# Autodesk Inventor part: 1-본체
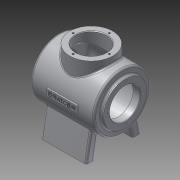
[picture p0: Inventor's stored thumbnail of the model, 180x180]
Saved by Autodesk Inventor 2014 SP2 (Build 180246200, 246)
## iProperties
Created: 2015-01
Part Number: 1-본체
Material: 알루미늄 6061
Document SubType Name: Modeling
Designer: 201-07
Density: 2.71 g/cm^3
Appearance: 알루미늄 - 평지
Mass: 1021.13 g
Surface Area: 1060.37 cm^2
Volume: 376.801 cm^3
Author: 201-07
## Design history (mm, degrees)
sketch "스케치1"
  geometry: C1 r 50 at (0, 0); 1 further point
  constraints: 1 centre point, 1 coincident
  dimensions: "d0" = 100 diameter of C1
extrude "돌출1" new body sketch "스케치1" stored distance "d1" = 112; taper "d2" = 0 deg
fillet "모깎기1" dims "d3" = 3
node "작업 평면1"
sketch "스케치2"
  geometry: C1 r 38 at (0, 0); 1 further point
  constraints: 1 centre point, 1 coincident
  dimensions: "d5" = 76 diameter of C1
extrude "돌출2" join sketch "스케치2" stored distance "d6" = 112; taper "d7" = 0 deg
fillet "모깎기2" dims "d8" = 3
fillet "모깎기3" dims "d9" = 3
hole "구멍1" diameter "d12" = 54; stored, may be unused: countersink angle "d16" = 90 deg, drill point angle "d18" = 0 deg; dims "d10" = 10, "d11" = 10, "d13" = 6, "d14" = 4, "d15" = 2, "d17" = 13
hole "구멍2" diameter "d21" = 90; stored, may be unused: countersink angle "d25" = 90 deg, drill point angle "d27" = 0 deg; dims "d19" = 10, "d20" = 10, "d22" = 6, "d23" = 4, "d24" = 2, "d26" = 97
hole "구멍3" diameter "d30" = 54; stored, may be unused: countersink angle "d34" = 90 deg, drill point angle "d36" = 0 deg; dims "d28" = 10, "d29" = 10, "d31" = 6, "d32" = 4, "d33" = 2, "d35" = 12
node "작업 평면2"
sketch "스케치3"
  geometry: L1 (-61, 38)-(-61, -38) reference; L2 (0, 0)-(1, 0); C1 r 38 at (1, 0)
  constraints: 2 end point, 1 centre point, 1 perpendicular
  dimensions: "d103" = 76 diameter of C1; "d104" = 62 distance from line of L1 L2.end
extrude "돌출3" join sketch "스케치3" stored distance "d39" = 112; taper "d40" = 0 deg
sketch "스케치5" dims "d62" = 64
  geometry: L1 (-32, 0)-(0, 0); 1 further point
  constraints: 2 end point, 1 coincident, 1 horizontal, 1 horizontal alignment, 2 other
hole "구멍6" sketch "스케치5" at (-32, 0) diameter "d63" = 3.242; stored, may be unused: countersink angle "d67" = 90 deg, drill point angle "d69" = 118 deg; dims "d64" = 8, "d65" = 4, "d66" = 2, "d68" = 10
chamfer "모따기1" distance "d73" = 1; stored, may be unused: second distance "d74" = 2, angle "d75" = 45 deg
fillet "모깎기5" dims "d76" = 3
node "작업 평면3"
sketch "스케치6"
  geometry: L1 (39.336, -30.865)-(48, -80); L2 (27.282, -41.901)-(34, -80); L3 (48, -80)-(34, -80); C1 r 45 at (0, 0) reference; A1 r 50 centre (0, 0) between (8.491, 49.274) and (-8.491, 49.274); A2 r 50 centre (0, 0) between (27.282, -41.901) and (39.336, -30.865); 2 further points
  constraints: 6 end point, 4 point on circle, 2 centre point, 1 coincident, 1 horizontal, 1 parallel, 2 other
  dimensions: "d78" = 80 distance from line of point (0, 0) L3; "d79" = 14 distance of L2.end L1.end; "d80" = 100 deg angle of L3 L1; "d81" = 80 deg angle of L3 L2 (derived); "d84" = 48 horizontal distance of point (0, 0) L1.end
extrude "돌출4" join sketch "스케치6" distance "d85" = 80; taper "d86" = 0 deg
fillet "모깎기6" dims "d87" = 3
node "작업 평면4"
sketch "스케치7"
  geometry: L1 (-26, 6)-(28, 6); L2 (28, 6)-(28, -6); L3 (28, -6)-(-26, -6); L4 (-26, -6)-(-26, 6); L5 (-26, 6)-(28, -6); L6 (28, 6)-(-26, -6); L7 (37, -80)-(-37, -80) reference; L8 (-61, 38)-(-61, -38) reference; 1 further point
  constraints: 12 end point, 2 midpoint, 2 parallel, 1 horizontal, 1 perpendicular
  dimensions: "d98" = 12 distance between parallel lines of L3 L1; "d99" = 54 distance between parallel lines of L4 L2; "d100" = 80 distance from line of L7 point (1, 0); "d101" = 62 distance from line of L8 point (1, 0)
extrude "돌출5" join sketch "스케치7" stored distance "d91" = 80; taper "d92" = 0 deg
sketch "스케치8"
  geometry: L1 (-23.887, 3.602)-(25.887, 3.602); L2 (25.887, 3.602)-(25.887, -3.602); L3 (25.887, -3.602)-(-23.887, -3.602); L4 (-23.887, -3.602)-(-23.887, 3.602); L5 (-23.887, 0)-(25.887, 0); L6 (1, 3.602)-(1, -3.602); L7 (37, -80)-(-37, -80) reference; L8 (-61, 38)-(-61, -38) reference; 1 further point
  constraints: 4 end point, 4 midpoint, 2 other
  dimensions: "d93" = 7.20489 distance of L6.start L6.end; "d94" = 49.77477 distance of L5.start L5.end; "d95" = 80 distance between parallel lines of L7 L5; "d102" = 62 distance between parallel lines of L8 L6
feature "엠보싱1" sketch "스케치8" dims "d9" = 3, "d96" = 0.5, "d97" = 0
hole "구멍7" diameter "d107" = 54; stored, may be unused: countersink angle "d111" = 90 deg, drill point angle "d113" = 0 deg; dims "d105" = 10, "d106" = 10, "d108" = 8, "d109" = 4, "d110" = 2, "d112" = 10
chamfer "모따기2" distance "d114" = 1; stored, may be unused: second distance "d115" = 2, angle "d116" = 45 deg
fillet "모깎기7" dims "d117" = 3
sketch "스케치9" dims "d119" = 64
  geometry: L1 (-62, 38)-(-62, -38) reference; L2 (-1, 0)-(0, 0); L3 (0, 32)-(0, 0)
  constraints: 4 end point, 2 perpendicular, 1 vertical alignment, 2 other
  dimensions: "d120" = 62 distance from line of L1 L2.end
hole "구멍8" sketch "스케치9" at (0, 32) diameter "d121" = 3.242; stored, may be unused: countersink angle "d125" = 90 deg, drill point angle "d127" = 118 deg; dims "d122" = 8, "d123" = 4, "d124" = 2, "d126" = 10
node "솔리드1"
mirror "대칭1"
pattern_circular "원형 패턴2" dims angle "d71" = 360 deg
mirror "대칭2"
mirror "대칭3"
pattern_circular "원형 패턴3" dims angle "d129" = 360 deg
node "절단 모서리 투영1"
other parameters: "d4" = 5, "d37" = 62, "d88" = -52
